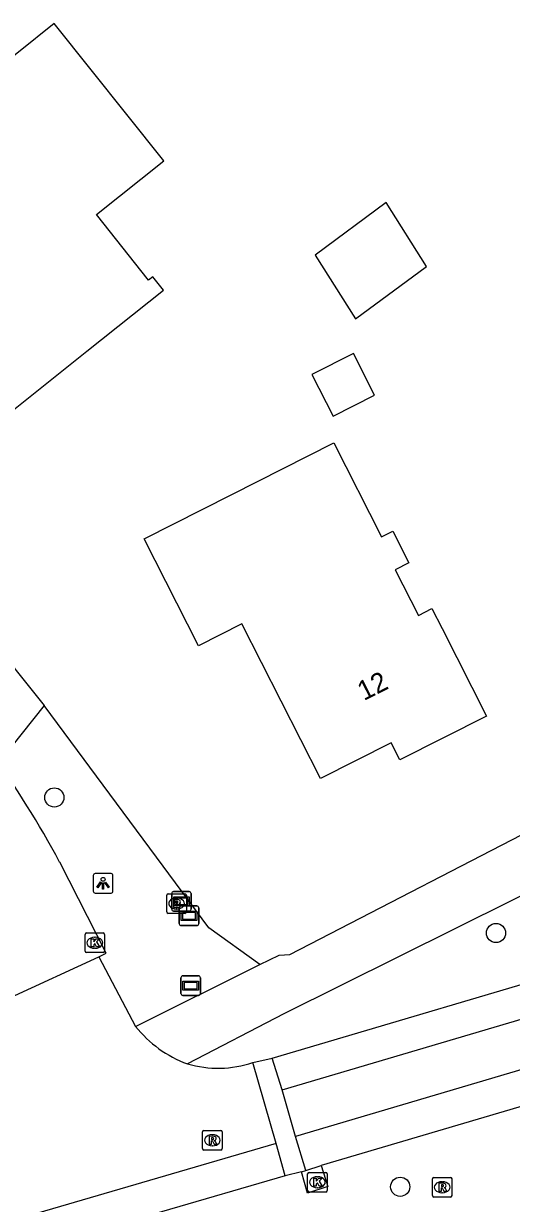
# Model space of a CAD drawing. Extents: x 162417 to 163721, y 384268 to 385416.
# Drawn here: x 163503.1 to 163527.9, y 384750.1 to 384810.2 of the extents above; entities that cross this region are included whole.
import ezdxf

# ---------------------------------------------------------------- set-up
doc = ezdxf.new("R2010")
doc.units = 0
for name, color, linetype in [('IMGEO_Berm_groen', 7, 'Continuous'), ('IMGEO_Boom', 7, 'Continuous'), ('IMGEO_Brandkraan', 7, 'Continuous'), ('IMGEO_Groenvoorziening', 7, 'Continuous'), ('IMGEO_Hek', 7, 'Continuous'), ('IMGEO_Kolk', 7, 'Continuous'), ('IMGEO_Lichtpunt', 7, 'Continuous'), ('IMGEO_Pand', 7, 'Continuous'), ('IMGEO_Pand_nummerreeks', 7, 'Continuous'), ('IMGEO_Rijbaan_lokaal_gesloten', 7, 'Continuous'), ('IMGEO_Rijbaan_lokaal_open', 7, 'Continuous'), ('IMGEO_Rioolput', 7, 'Continuous'), ('IMGEO_Straatnaambord', 7, 'Continuous'), ('IMGEO_Verklikker', 7, 'Continuous'), ('IMGEO_Voetpad_open', 7, 'Continuous')]:
    doc.layers.add(name, color=color, linetype=linetype)

msp = doc.modelspace()

# ---------------------------------------------------------------- linework, layer by layer
at = {"layer": 'IMGEO_Berm_groen'}
msp.add_lwpolyline([(163515.109, 384762.248), (163512.497, 384764.123), (163504.115, 384775.46)], dxfattribs=at)
at = {"layer": 'IMGEO_Boom'}
for centre in [(163504.629, 384770.766), (163527.134, 384763.854), (163522.256, 384750.916)]:
    msp.add_circle(centre, 0.489, dxfattribs=at)
at = {"layer": 'IMGEO_Brandkraan'}
for p, q in [((163510.431, 384765.857), (163511.283, 384765.857)), ((163510.356, 384764.931), (163510.356, 384765.783)), ((163510.844, 384765.637), (163510.869, 384765.637)), ((163511.357, 384765.783), (163511.357, 384764.931)), ((163511.283, 384764.857), (163510.431, 384764.857)), ((163510.867, 384765.077), (163510.842, 384765.077))]:
    msp.add_line(p, q, dxfattribs=at)
for points in [[(163510.431, 384765.857), (163511.283, 384765.857)], [(163510.356, 384764.931), (163510.356, 384765.783)], [(163510.704, 384765.557), (163510.704, 384765.157), (163510.917, 384765.157)], [(163510.935, 384765.557), (163510.704, 384765.557)], [(163510.883, 384765.476), (163510.829, 384765.476), (163510.829, 384765.4)], [(163510.829, 384765.4), (163510.882, 384765.4)], [(163510.891, 384765.324), (163510.829, 384765.324), (163510.829, 384765.243)], [(163510.829, 384765.243), (163510.891, 384765.243)], [(163511.357, 384765.783), (163511.357, 384764.931)], [(163511.283, 384764.857), (163510.431, 384764.857)]]:
    msp.add_lwpolyline(points, dxfattribs=at)
for centre, radius, start, end in [((163510.433, 384765.781), 0.0765, 91.55205, 178.44795), ((163510.433, 384765.781), 0.0765, 91.55205, 178.44795), ((163511.281, 384765.781), 0.0765, 1.55205, 88.44795), ((163511.281, 384765.781), 0.0765, 1.55205, 88.44795), ((163510.884, 384765.438), 0.0379, 267.82845, 90.93552), ((163510.892, 384765.283), 0.0404, 269.87594, 90.50774), ((163510.939, 384765.412), 0.145, 59.4692, 91.53667), ((163510.964, 384765.459), 0.0922, 285.51372, 58.15012), ((163510.969, 384765.267), 0.105, 301.31148, 78.98903), ((163510.433, 384764.933), 0.0765, 181.55205, 268.44795), ((163510.433, 384764.933), 0.0765, 181.55205, 268.44795), ((163510.923, 384765.408), 0.251, 268.66757, 293.53466), ((163511.281, 384764.933), 0.0765, 271.55205, 358.44795), ((163511.281, 384764.933), 0.0765, 271.55205, 358.44795)]:
    msp.add_arc(centre, radius, start, end, dxfattribs=at)
for centre, major_axis, ratio, start_param, end_param in [((163510.843, 384765.357), (-0.387, 0.002), 0.722429, 4.712389, 7.853982), ((163510.868, 384765.357), (-0.39, 0.002), 0.717154, 1.570796, 4.712389)]:
    msp.add_ellipse(centre, major_axis=major_axis, ratio=ratio, start_param=start_param, end_param=end_param, dxfattribs=at)
at = {"layer": 'IMGEO_Groenvoorziening'}
msp.add_lwpolyline([(163518.228, 384751.997), (163518.558, 384750.929), (163517.538, 384750.583), (163517.216, 384751.678)], dxfattribs=at)
at = {"layer": 'IMGEO_Hek'}
msp.add_lwpolyline([(163515.109, 384762.248), (163512.497, 384764.123), (163504.115, 384775.46)], dxfattribs=at)
at = {"layer": 'IMGEO_Kolk'}
for p, q in [((163506.192, 384762.93), (163506.192, 384763.782)), ((163506.267, 384763.856), (163507.119, 384763.856)), ((163506.68, 384763.636), (163506.705, 384763.636)), ((163507.193, 384763.782), (163507.193, 384762.93)), ((163507.119, 384762.856), (163506.267, 384762.856)), ((163506.703, 384763.076), (163506.678, 384763.076)), ((163517.535, 384750.723), (163517.535, 384751.575)), ((163517.61, 384751.649), (163518.462, 384751.649)), ((163518.023, 384751.429), (163518.048, 384751.429)), ((163518.536, 384751.575), (163518.536, 384750.723)), ((163518.046, 384750.869), (163518.021, 384750.869)), ((163518.462, 384750.649), (163517.61, 384750.649))]:
    msp.add_line(p, q, dxfattribs=at)
for points in [[(163506.192, 384762.93), (163506.192, 384763.782)], [(163506.267, 384763.856), (163507.119, 384763.856)], [(163506.513, 384763.556), (163506.636, 384763.556), (163506.636, 384763.405), (163506.766, 384763.556), (163506.93, 384763.556), (163506.784, 384763.405), (163506.937, 384763.156), (163506.785, 384763.156), (163506.7, 384763.32), (163506.636, 384763.253), (163506.636, 384763.156), (163506.513, 384763.156), (163506.513, 384763.556)], [(163507.193, 384763.782), (163507.193, 384762.93)], [(163507.119, 384762.856), (163506.267, 384762.856)], [(163517.535, 384750.723), (163517.535, 384751.575)], [(163517.61, 384751.649), (163518.462, 384751.649)], [(163517.856, 384751.349), (163517.979, 384751.349), (163517.979, 384751.198), (163518.109, 384751.349), (163518.273, 384751.349), (163518.127, 384751.198), (163518.28, 384750.949), (163518.128, 384750.949), (163518.043, 384751.113), (163517.979, 384751.046), (163517.979, 384750.949), (163517.856, 384750.949), (163517.856, 384751.349)], [(163518.536, 384751.575), (163518.536, 384750.723)], [(163518.462, 384750.649), (163517.61, 384750.649)]]:
    msp.add_lwpolyline(points, dxfattribs=at)
for centre, start, end in [((163506.269, 384763.78), 91.55205, 178.44795), ((163506.269, 384763.78), 91.55205, 178.44795), ((163507.117, 384763.78), 1.55205, 88.44795), ((163507.117, 384763.78), 1.55205, 88.44795), ((163506.269, 384762.932), 181.55205, 268.44795), ((163506.269, 384762.932), 181.55205, 268.44795), ((163507.117, 384762.932), 271.55205, 358.44795), ((163507.117, 384762.932), 271.55205, 358.44795), ((163517.612, 384751.573), 91.55205, 178.44795), ((163517.612, 384751.573), 91.55205, 178.44795), ((163518.46, 384751.573), 1.55205, 88.44795), ((163518.46, 384751.573), 1.55205, 88.44795), ((163517.612, 384750.725), 181.55205, 268.44795), ((163517.612, 384750.725), 181.55205, 268.44795), ((163518.46, 384750.725), 271.55205, 358.44795), ((163518.46, 384750.725), 271.55205, 358.44795)]:
    msp.add_arc(centre, 0.0765, start, end, dxfattribs=at)
for centre, major_axis, ratio, start_param, end_param in [((163506.679, 384763.356), (-0.387, 0.002), 0.722429, 4.712389, 7.853982), ((163506.704, 384763.356), (-0.39, 0.002), 0.717154, 1.570796, 4.712389), ((163518.022, 384751.149), (-0.387, 0.002), 0.722429, 4.712389, 7.853982), ((163518.047, 384751.149), (-0.39, 0.002), 0.717154, 1.570796, 4.712389)]:
    msp.add_ellipse(centre, major_axis=major_axis, ratio=ratio, start_param=start_param, end_param=end_param, dxfattribs=at)
at = {"layer": 'IMGEO_Lichtpunt'}
for p, q in [((163506.616, 384766.793), (163506.616, 384765.986)), ((163506.616, 384766.793), (163506.616, 384765.986)), ((163507.518, 384766.888), (163506.71, 384766.888)), ((163507.518, 384766.888), (163506.71, 384766.888)), ((163507.612, 384765.986), (163507.612, 384766.793)), ((163507.612, 384765.986), (163507.612, 384766.793)), ((163506.71, 384765.892), (163507.518, 384765.892)), ((163506.71, 384765.892), (163507.518, 384765.892))]:
    msp.add_line(p, q, dxfattribs=at)
for points in [[(163506.99, 384766.457), (163507.029, 384766.429), (163506.841, 384766.167), (163506.803, 384766.194), (163506.99, 384766.457)], [(163507.092, 384766.409), (163507.139, 384766.409), (163507.139, 384766.087), (163507.092, 384766.087), (163507.092, 384766.409)], [(163507.202, 384766.429), (163507.24, 384766.456), (163507.427, 384766.194), (163507.388, 384766.166), (163507.202, 384766.429)]]:
    msp.add_lwpolyline(points, dxfattribs=at)
msp.add_circle((163507.115, 384766.591), 0.0994, dxfattribs=at)
for centre, start, end in [((163506.71, 384766.793), 90, 180), ((163506.71, 384766.793), 90, 180), ((163507.518, 384766.793), 0, 90), ((163507.518, 384766.793), 0, 90), ((163506.71, 384765.986), 180, 270), ((163506.71, 384765.986), 180, 270), ((163507.518, 384765.986), 270, 0), ((163507.518, 384765.986), 270, 360)]:
    msp.add_arc(centre, 0.0946, start, end, dxfattribs=at)
at = {"layer": 'IMGEO_Pand'}
for points in [[(163499.081, 384805.352), (163500, 384804.2), (163502.157, 384801.496), (163500.406, 384800.099), (163500, 384799.776), (163496.883, 384797.291), (163500, 384793.381), (163502.375, 384790.402), (163506.285, 384793.52), (163510.196, 384796.638), (163509.651, 384797.321), (163509.436, 384797.15), (163506.776, 384800.487), (163510.205, 384803.221), (163504.62, 384810.226), (163502.796, 384808.772), (163500, 384806.543), (163498.857, 384805.632)], [(163517.928, 384798.42), (163519.979, 384795.165), (163523.592, 384797.848), (163521.541, 384801.103), (163517.928, 384798.42)], [(163517.756, 384792.333), (163518.835, 384790.203), (163520.949, 384791.273), (163519.87, 384793.404), (163517.756, 384792.333)], [(163518.872, 384788.853), (163521.299, 384784.062), (163521.872, 384784.353), (163522.698, 384782.722), (163522.004, 384782.371), (163523.179, 384780.051), (163523.873, 384780.403), (163524.393, 384779.377), (163526.653, 384774.917), (163522.24, 384772.68), (163521.795, 384773.558), (163518.19, 384771.731), (163514.191, 384779.623), (163511.977, 384778.502), (163509.213, 384783.958), (163513.673, 384786.218), (163518.872, 384788.853)]]:
    msp.add_lwpolyline(points, dxfattribs=at)
at = {"layer": 'IMGEO_Rijbaan_lokaal_gesloten'}
for points in [[(163516.247, 384755.862), (163568.591, 384771.342)], [(163569.328, 384768.997), (163516.926, 384753.474)], [(163506.897, 384762.633), (163507.272, 384762.826), (163504.901, 384767.474)], [(163502.394, 384760.57), (163506.897, 384762.633)], [(163515.737, 384757.479), (163533.078, 384762.613)], [(163538.37, 384757.945), (163518.228, 384751.997)], [(163515.925, 384753.114), (163476.086, 384741.478), (163476.579, 384739.761)], [(163517.439, 384751.748), (163518.228, 384751.997)], [(163516.394, 384751.472), (163510.098, 384749.633), (163505.104, 384748.146)]]:
    msp.add_lwpolyline(points, dxfattribs=at)
msp.add_arc((163452.637, 384739.058), 59.489, 28.53289, 34.93086, dxfattribs=at)
at = {"layer": 'IMGEO_Rijbaan_lokaal_open'}
for points in [[(163506.897, 384762.633), (163508.773, 384759.09)], [(163514.748, 384757.246), (163515.737, 384757.479)], [(163516.247, 384755.862), (163515.737, 384757.479)], [(163515.925, 384753.114), (163514.748, 384757.246)], [(163516.926, 384753.474), (163516.247, 384755.862)], [(163517.439, 384751.748), (163516.926, 384753.474)], [(163516.394, 384751.472), (163515.925, 384753.114)], [(163517.216, 384751.678), (163516.394, 384751.472)], [(163517.216, 384751.678), (163517.439, 384751.748)]]:
    msp.add_lwpolyline(points, dxfattribs=at)
for centre, radius, start, end in [((163513.483, 384762.823), 6.01, 218.40154, 249.82326), ((163512.975, 384762.615), 5.654, 253.92588, 288.27093)]:
    msp.add_arc(centre, radius, start, end, dxfattribs=at)
at = {"layer": 'IMGEO_Rioolput'}
for p, q in [((163512.255, 384753.788), (163513.107, 384753.788)), ((163512.18, 384752.862), (163512.18, 384753.714)), ((163512.668, 384753.568), (163512.693, 384753.568)), ((163513.181, 384753.714), (163513.181, 384752.862)), ((163513.107, 384752.788), (163512.255, 384752.788)), ((163512.691, 384753.008), (163512.666, 384753.008)), ((163523.967, 384751.394), (163524.819, 384751.394)), ((163523.892, 384750.468), (163523.892, 384751.32)), ((163524.38, 384751.174), (163524.405, 384751.174)), ((163524.893, 384751.32), (163524.893, 384750.468)), ((163524.819, 384750.394), (163523.967, 384750.394)), ((163524.403, 384750.614), (163524.378, 384750.614))]:
    msp.add_line(p, q, dxfattribs=at)
for points in [[(163512.255, 384753.788), (163513.107, 384753.788)], [(163512.18, 384752.862), (163512.18, 384753.714)], [(163512.769, 384753.486), (163512.517, 384753.488), (163512.517, 384753.088)], [(163512.517, 384753.088), (163512.641, 384753.088), (163512.641, 384753.25), (163512.652, 384753.25)], [(163512.695, 384753.407), (163512.641, 384753.407), (163512.641, 384753.326)], [(163512.641, 384753.326), (163512.693, 384753.326)], [(163512.699, 384753.221), (163512.77, 384753.088), (163512.91, 384753.088), (163512.845, 384753.214)], [(163513.181, 384753.714), (163513.181, 384752.862)], [(163513.107, 384752.788), (163512.255, 384752.788)], [(163523.967, 384751.394), (163524.819, 384751.394)], [(163523.892, 384750.468), (163523.892, 384751.32)], [(163524.481, 384751.092), (163524.229, 384751.094), (163524.229, 384750.694)], [(163524.229, 384750.694), (163524.353, 384750.694), (163524.353, 384750.856), (163524.364, 384750.856)], [(163524.407, 384751.013), (163524.353, 384751.013), (163524.353, 384750.932)], [(163524.353, 384750.932), (163524.405, 384750.932)], [(163524.411, 384750.827), (163524.482, 384750.694), (163524.622, 384750.694), (163524.557, 384750.82)], [(163524.893, 384751.32), (163524.893, 384750.468)], [(163524.819, 384750.394), (163523.967, 384750.394)]]:
    msp.add_lwpolyline(points, dxfattribs=at)
for centre, radius, start, end in [((163512.257, 384753.712), 0.0765, 91.55205, 178.44795), ((163512.257, 384753.712), 0.0765, 91.55205, 178.44795), ((163513.105, 384753.712), 0.0765, 1.55205, 88.44795), ((163513.105, 384753.712), 0.0765, 1.55205, 88.44795), ((163512.651, 384753.197), 0.0533, 26.02933, 88.69889), ((163512.677, 384753.515), 0.19, 274.7715, 282.96867), ((163512.701, 384753.311), 0.0964, 77.00612, 93.18647), ((163512.715, 384753.368), 0.0378, 276.66336, 79.67722), ((163512.768, 384753.376), 0.109, 350.36119, 89.41601), ((163512.766, 384753.376), 0.112, 277.58423, 350.98172), ((163512.75, 384753.161), 0.108, 29.51342, 73.79051), ((163512.257, 384752.864), 0.0765, 181.55205, 268.44795), ((163512.257, 384752.864), 0.0765, 181.55205, 268.44795), ((163513.105, 384752.864), 0.0765, 271.55205, 358.44795), ((163513.105, 384752.864), 0.0765, 271.55205, 358.44795), ((163523.969, 384751.318), 0.0765, 91.55205, 178.44795), ((163523.969, 384751.318), 0.0765, 91.55205, 178.44795), ((163524.817, 384751.318), 0.0765, 1.55205, 88.44795), ((163524.817, 384751.318), 0.0765, 1.55205, 88.44795), ((163524.363, 384750.803), 0.0533, 26.02933, 88.69889), ((163524.389, 384751.121), 0.19, 274.7715, 282.96867), ((163524.413, 384750.917), 0.0964, 77.00612, 93.18647), ((163524.427, 384750.974), 0.0378, 276.66336, 79.67722), ((163524.48, 384750.982), 0.109, 350.36119, 89.41601), ((163524.478, 384750.982), 0.112, 277.58423, 350.98172), ((163524.462, 384750.767), 0.108, 29.51342, 73.79051), ((163523.969, 384750.47), 0.0765, 181.55205, 268.44795), ((163523.969, 384750.47), 0.0765, 181.55205, 268.44795), ((163524.817, 384750.47), 0.0765, 271.55205, 358.44795), ((163524.817, 384750.47), 0.0765, 271.55205, 358.44795)]:
    msp.add_arc(centre, radius, start, end, dxfattribs=at)
for centre, major_axis, ratio, start_param, end_param in [((163512.667, 384753.288), (-0.387, 0.002), 0.722429, 4.712389, 7.853982), ((163512.692, 384753.288), (-0.39, 0.002), 0.717154, 1.570796, 4.712389), ((163524.379, 384750.894), (-0.387, 0.002), 0.722429, 4.712389, 7.853982), ((163524.404, 384750.894), (-0.39, 0.002), 0.717154, 1.570796, 4.712389)]:
    msp.add_ellipse(centre, major_axis=major_axis, ratio=ratio, start_param=start_param, end_param=end_param, dxfattribs=at)
at = {"layer": 'IMGEO_Straatnaambord'}
for p, q in [((163511.179, 384761.672), (163511.969, 384761.672)), ((163511.969, 384761.672), (163511.179, 384761.672)), ((163511.079, 384760.772), (163511.079, 384761.572)), ((163511.079, 384761.572), (163511.079, 384760.772)), ((163512.069, 384761.572), (163512.069, 384760.772)), ((163512.069, 384760.772), (163512.069, 384761.572)), ((163511.969, 384760.672), (163511.179, 384760.672)), ((163511.179, 384760.672), (163511.969, 384760.672))]:
    msp.add_line(p, q, dxfattribs=at)
for points in [[(163511.18, 384761.404), (163511.968, 384761.404), (163511.968, 384760.94), (163511.18, 384760.94), (163511.18, 384761.404)], [(163511.245, 384761.339), (163511.245, 384761.005), (163511.903, 384761.005), (163511.903, 384761.339), (163511.245, 384761.339)]]:
    msp.add_lwpolyline(points, dxfattribs=at)
for centre, start, end in [((163511.179, 384761.572), 90, 180), ((163511.179, 384761.572), 90, 180), ((163511.969, 384761.572), 0, 90), ((163511.969, 384761.572), 360, 90), ((163511.179, 384760.772), 180, 270), ((163511.179, 384760.772), 180, 270), ((163511.969, 384760.772), 270, 0), ((163511.969, 384760.772), 270, 0)]:
    msp.add_arc(centre, 0.1, start, end, dxfattribs=at)
at = {"layer": 'IMGEO_Verklikker'}
for p, q in [((163510.61, 384765.07), (163510.61, 384765.87)), ((163510.61, 384765.87), (163510.61, 384765.07)), ((163510.71, 384765.97), (163511.5, 384765.97)), ((163511.5, 384765.97), (163510.71, 384765.97)), ((163511.6, 384765.87), (163511.6, 384765.07)), ((163511.6, 384765.07), (163511.6, 384765.87)), ((163511.098, 384765.233), (163511.888, 384765.233)), ((163511.888, 384765.233), (163511.098, 384765.233)), ((163511.5, 384764.97), (163510.71, 384764.97)), ((163510.71, 384764.97), (163511.5, 384764.97)), ((163510.998, 384764.333), (163510.998, 384765.133)), ((163510.998, 384765.133), (163510.998, 384764.333)), ((163511.988, 384765.133), (163511.988, 384764.333)), ((163511.988, 384764.333), (163511.988, 384765.133)), ((163511.888, 384764.233), (163511.098, 384764.233)), ((163511.098, 384764.233), (163511.888, 384764.233))]:
    msp.add_line(p, q, dxfattribs=at)
for points in [[(163510.711, 384765.702), (163511.499, 384765.702), (163511.499, 384765.238), (163510.711, 384765.238), (163510.711, 384765.702)], [(163510.776, 384765.637), (163510.776, 384765.303), (163511.434, 384765.303), (163511.434, 384765.637), (163510.776, 384765.637)], [(163511.099, 384764.965), (163511.887, 384764.965), (163511.887, 384764.501), (163511.099, 384764.501), (163511.099, 384764.965)], [(163511.164, 384764.9), (163511.164, 384764.566), (163511.822, 384764.566), (163511.822, 384764.9), (163511.164, 384764.9)]]:
    msp.add_lwpolyline(points, dxfattribs=at)
for centre, start, end in [((163510.71, 384765.87), 90, 180), ((163510.71, 384765.87), 90, 180), ((163511.5, 384765.87), 0, 90), ((163511.5, 384765.87), 360, 90), ((163511.098, 384765.133), 90, 180), ((163511.098, 384765.133), 90, 180), ((163511.888, 384765.133), 0, 90), ((163511.888, 384765.133), 360, 90), ((163510.71, 384765.07), 180, 270), ((163510.71, 384765.07), 180, 270), ((163511.5, 384765.07), 270, 0), ((163511.5, 384765.07), 270, 0), ((163511.098, 384764.333), 180, 270), ((163511.098, 384764.333), 180, 270), ((163511.888, 384764.333), 270, 0), ((163511.888, 384764.333), 270, 0)]:
    msp.add_arc(centre, 0.1, start, end, dxfattribs=at)
at = {"layer": 'IMGEO_Voetpad_open'}
for points in [[(163515.109, 384762.248), (163516.079, 384762.732), (163516.622, 384762.752), (163544.387, 384777.107), (163568.118, 384789.259)], [(163501.192, 384779.094), (163504.115, 384775.46)], [(163504.115, 384775.46), (163501.871, 384772.635), (163501.409, 384773.121)], [(163530.914, 384766.989), (163516.316, 384759.734), (163511.41, 384757.182)], [(163508.773, 384759.09), (163515.109, 384762.248)]]:
    msp.add_lwpolyline(points, dxfattribs=at)

# ---------------------------------------------------------------- texts
at = {"layer": 'IMGEO_Pand_nummerreeks'}
msp.add_text('12', height=1, rotation=26.87571, dxfattribs=at).set_placement((163520.401, 384775.677))

doc.saveas('drawing.dxf')
